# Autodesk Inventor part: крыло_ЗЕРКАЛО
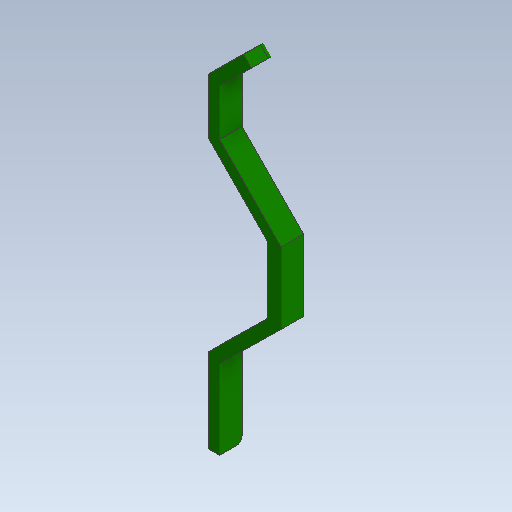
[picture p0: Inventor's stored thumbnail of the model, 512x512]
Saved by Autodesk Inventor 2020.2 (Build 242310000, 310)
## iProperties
Created: 2020-04
Part Number: крыло_ЗЕРКАЛО
Material: Типовые
Document SubType Name: Modeling
Designer: Алексей
Density: 1 g/cm^3
Appearance: По умолчанию
Author: Алексей
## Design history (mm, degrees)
derived "крыло.ipt"
  sketch "Эскиз1"
    geometry: L1 (-11, -78)-(-4.414, -78) reference; L2 (-11, -78)-(-11, -74) reference; L3 (-11, -74)-(-25, -74) reference; L4 (-25, -74)-(-25, -78) reference; L5 (-35, -78)-(-25, -78) reference; L6 (-35, -58)-(-35, -78) reference; L7 (-28.375, -58)-(-35, -58) reference; L8 (-35, -18)-(-28.375, -18) reference; L9 (-35, -2)-(-35, -18) reference; L10 (-35, -2)-(-31, -2) reference; L11 (-31, -2)-(-31, 12) reference; L12 (-31, 12)-(-35, 12) reference; L13 (-35, 28)-(-35, 12) reference; L14 (-28.375, 28)-(-35, 28) reference; L15 (-35, 68)-(-28.375, 68) reference; L16 (-35, 78)-(-35, 68) reference; L17 (-22, 78)-(-35, 78) reference; L18 (-22, 78)-(-22, 74) reference; L19 (-22, 74)-(-8, 74) reference; L20 (-8, 74)-(-8, 78) reference; L21 (5, 78)-(-8, 78) reference; L22 (7.718, 70.105)-(5, 78) reference; L23 (12.5, 67)-(7.718, 70.105) reference; L24 (13.093, 60.719)-(12.5, 67) reference; L25 (13.093, 60.719)-(9.11, 60.343) reference; L26 (9.11, 60.343)-(10.425, 46.405) reference; L27 (10.425, 46.405)-(14.407, 46.781) reference; L28 (15, 40.5)-(14.407, 46.781) reference; L29 (4.88, 34.8)-(15, 40.5) reference; L30 (2.58, 25.5)-(4.88, 34.8) reference; L31 (15.736, -18.735)-(8.938, -18.9) reference; L32 (34.328, -10.306)-(15.736, -18.735) reference; L33 (35, -16.306)-(34.328, -10.306) reference; L34 (26.476, -21.507)-(35, -16.306) reference; L35 (26.476, -21.507)-(24.392, -18.092) reference; L36 (24.392, -18.092)-(12.441, -25.384) reference; L37 (12.441, -25.384)-(14.524, -28.799) reference; L38 (6, -34)-(14.524, -28.799) reference; L39 (3.6, -49.087)-(6, -34) reference; L40 (3.6, -49.087)-(-0.351, -48.458) reference; L41 (-0.351, -48.458)-(-2.55, -62.285) reference; L42 (-2.55, -62.285)-(1.4, -62.913) reference; L43 (-0.464, -74.628)-(1.4, -62.913) reference; L44 (-8.375, -58)-(-8.375, -29.617) reference; L45 (-8.375, -29.617)-(-30.337, -8.02) reference; L46 (-30.337, -8.02)-(-30.337, 17.48) reference; L47 (-30.337, 17.48)-(-8.375, 39.814) reference; L48 (-8.375, 39.814)-(-8.375, 56.383) reference; L49 (-8.375, 56.383)-(-19.747, 67.565) reference; L50 (-19.747, 67.565)-(-16.942, 70.417) reference; L51 (-16.942, 70.417)-(-4.375, 58.059) reference; L52 (-4.375, 58.059)-(-4.375, 38.177) reference; L53 (-4.375, 38.177)-(-25.343, 16.854) reference; L54 (-25.343, 16.854)-(-25.343, -7.321) reference; L55 (-25.343, -7.321)-(-4.375, -27.941) reference; L56 (-4.375, -27.941)-(-4.375, -58) reference; L57 (-4.375, -58)-(-8.375, -58) reference; L58 (2.58, 25.5)-(-15.848, 15.1) reference; L59 (-15.848, 15.1)-(-20.343, 10.529) reference; L60 (-20.343, 10.529)-(-20.343, -5.226) reference; L61 (-20.343, -5.226)-(-6.438, -18.9) reference; L62 (-6.438, -18.9)-(8.938, -18.9) reference; A1 r 4 centre (-4.414, -74) between (-4.414, -78) and (-0.464, -74.628) reference; A2 r 20 centre (-28.375, -38) between (-28.375, -58) and (-28.375, -18) reference; A3 r 20 centre (-28.375, 48) between (-28.375, 28) and (-28.375, 68) reference; 1 further point
feature "Твердое тело1::крыло.ipt" dims "d0" = 10
tag "Элемент создания тегов1"
node "Твердое тело1"
